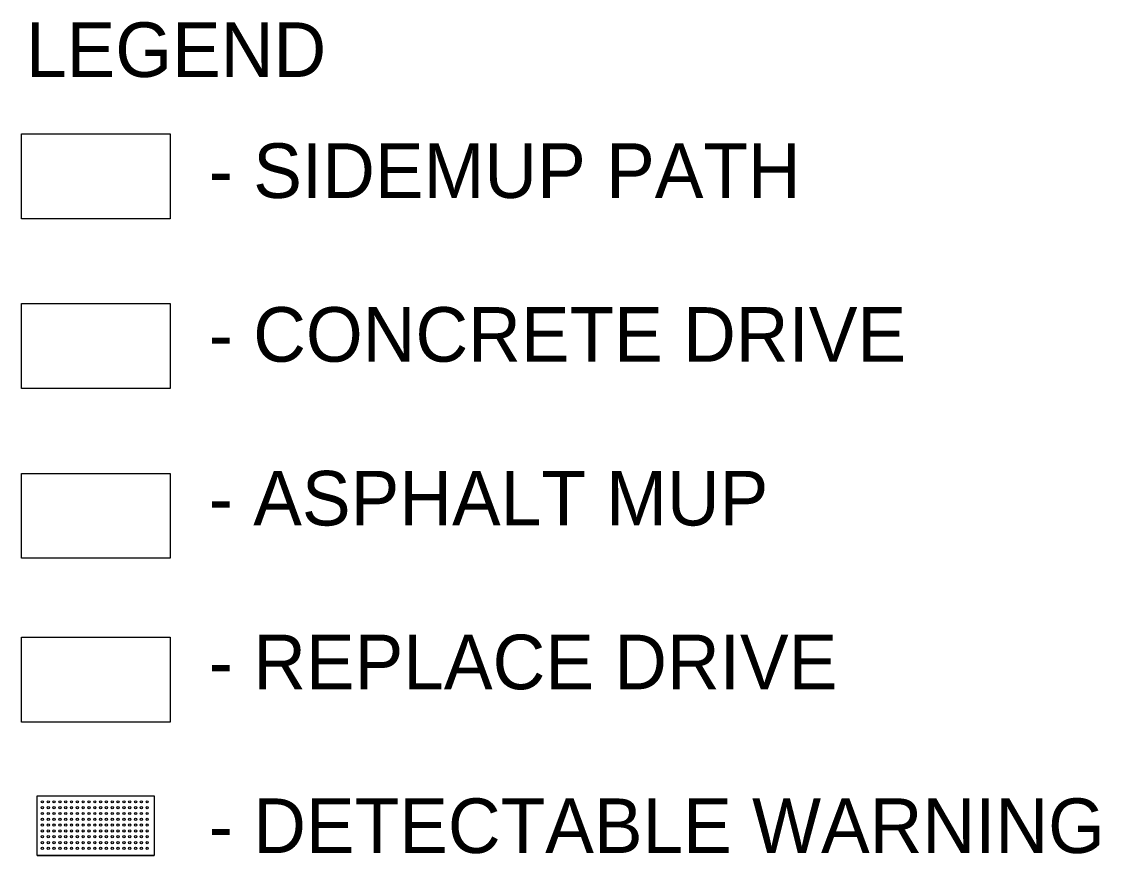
# Model space of a CAD drawing. Extents: x 1387347 to 1392798, y 437934 to 438772.
# Drawn here: x 1389672.4 to 1389727.7, y 438056.4 to 438099.2 of the extents above; entities that cross this region are included whole.
import ezdxf

# ---------------------------------------------------------------- set-up
doc = ezdxf.new("R2010")
doc.units = 0
for name, color, linetype in [('Default', 7, 'Continuous'), ('SC_Scratch6', 7, 'Continuous'), ('SC_Shading1', 7, 'Continuous'), ('SH_Text', 7, 'Continuous')]:
    doc.layers.add(name, color=color, linetype=linetype)

msp = doc.modelspace()

# ---------------------------------------------------------------- linework, layer by layer
at = {"layer": 'Default'}
for p, q in [((1389673.243, 438059.48), (1389679.243, 438059.48)), ((1389673.243, 438056.431), (1389679.243, 438056.431))]:
    msp.add_line(p, q, dxfattribs=at)
for centre in [(1389673.507, 438059.181), (1389673.507, 438058.883), (1389673.805, 438059.181), (1389673.805, 438058.883), (1389674.104, 438059.181), (1389674.104, 438058.883), (1389674.402, 438059.181), (1389674.402, 438058.883), (1389674.701, 438059.181), (1389674.701, 438058.883), (1389674.999, 438059.181), (1389674.999, 438058.883), (1389675.298, 438059.181), (1389675.298, 438058.883), (1389675.596, 438059.181), (1389675.596, 438058.883), (1389675.895, 438059.181), (1389675.895, 438058.883), (1389676.193, 438059.181), (1389676.193, 438058.883), (1389676.492, 438059.181), (1389676.492, 438058.883), (1389676.79, 438059.181), (1389676.79, 438058.883), (1389677.089, 438059.181), (1389677.089, 438058.883), (1389677.387, 438059.181), (1389677.387, 438058.883), (1389677.686, 438059.181), (1389677.686, 438058.883), (1389677.984, 438059.181), (1389677.984, 438058.883), (1389678.283, 438059.181), (1389678.283, 438058.883), (1389678.581, 438059.181), (1389678.581, 438058.883), (1389678.88, 438059.181), (1389678.88, 438058.883), (1389673.507, 438058.584), (1389673.507, 438058.286), (1389673.805, 438058.584), (1389673.805, 438058.286), (1389674.104, 438058.584), (1389674.104, 438058.286), (1389674.402, 438058.584), (1389674.402, 438058.286), (1389674.701, 438058.584), (1389674.701, 438058.286), (1389674.999, 438058.584), (1389674.999, 438058.286), (1389675.298, 438058.584), (1389675.298, 438058.286), (1389675.596, 438058.584), (1389675.596, 438058.286), (1389675.895, 438058.584), (1389675.895, 438058.286), (1389676.193, 438058.584), (1389676.193, 438058.286), (1389676.492, 438058.584), (1389676.492, 438058.286), (1389676.79, 438058.584), (1389676.79, 438058.286), (1389677.089, 438058.584), (1389677.089, 438058.286), (1389677.387, 438058.584), (1389677.387, 438058.286), (1389677.686, 438058.584), (1389677.686, 438058.286), (1389677.984, 438058.584), (1389677.984, 438058.286), (1389678.283, 438058.584), (1389678.283, 438058.286), (1389678.581, 438058.584), (1389678.581, 438058.286), (1389678.88, 438058.584), (1389678.88, 438058.286), (1389673.507, 438057.987), (1389673.507, 438057.689), (1389673.805, 438057.987), (1389673.805, 438057.689), (1389674.104, 438057.987), (1389674.104, 438057.689), (1389674.402, 438057.987), (1389674.402, 438057.689), (1389674.701, 438057.987), (1389674.701, 438057.689), (1389674.999, 438057.987), (1389674.999, 438057.689), (1389675.298, 438057.987), (1389675.298, 438057.689), (1389675.596, 438057.987), (1389675.596, 438057.689), (1389675.895, 438057.987), (1389675.895, 438057.689), (1389676.193, 438057.987), (1389676.193, 438057.689), (1389676.492, 438057.987), (1389676.492, 438057.689), (1389676.79, 438057.987), (1389676.79, 438057.689), (1389677.089, 438057.987), (1389677.089, 438057.689), (1389677.387, 438057.987), (1389677.387, 438057.689), (1389677.686, 438057.987), (1389677.686, 438057.689), (1389677.984, 438057.987), (1389677.984, 438057.689), (1389678.283, 438057.987), (1389678.283, 438057.689), (1389678.581, 438057.987), (1389678.581, 438057.689), (1389678.88, 438057.987), (1389678.88, 438057.689), (1389673.507, 438057.39), (1389673.507, 438057.092), (1389673.805, 438057.39), (1389673.805, 438057.092), (1389674.104, 438057.39), (1389674.104, 438057.092), (1389674.402, 438057.39), (1389674.402, 438057.092), (1389674.701, 438057.39), (1389674.701, 438057.092), (1389674.999, 438057.39), (1389674.999, 438057.092), (1389675.298, 438057.39), (1389675.298, 438057.092), (1389675.596, 438057.39), (1389675.596, 438057.092), (1389675.895, 438057.39), (1389675.895, 438057.092), (1389676.193, 438057.39), (1389676.193, 438057.092), (1389676.492, 438057.39), (1389676.492, 438057.092), (1389676.79, 438057.39), (1389676.79, 438057.092), (1389677.089, 438057.39), (1389677.089, 438057.092), (1389677.387, 438057.39), (1389677.387, 438057.092), (1389677.686, 438057.39), (1389677.686, 438057.092), (1389677.984, 438057.39), (1389677.984, 438057.092), (1389678.283, 438057.39), (1389678.283, 438057.092), (1389678.581, 438057.39), (1389678.581, 438057.092), (1389678.88, 438057.39), (1389678.88, 438057.092), (1389673.507, 438056.793), (1389673.805, 438056.793), (1389674.104, 438056.793), (1389674.402, 438056.793), (1389674.701, 438056.793), (1389674.999, 438056.793), (1389675.298, 438056.793), (1389675.596, 438056.793), (1389675.895, 438056.793), (1389676.193, 438056.793), (1389676.492, 438056.793), (1389676.79, 438056.793), (1389677.089, 438056.793), (1389677.387, 438056.793), (1389677.686, 438056.793), (1389677.984, 438056.793), (1389678.283, 438056.793), (1389678.581, 438056.793), (1389678.88, 438056.793)]:
    msp.add_circle(centre, 0.0572, dxfattribs=at)
at = {"layer": 'SC_Scratch6'}
msp.add_lwpolyline([(1389672.435, 438076.028), (1389680.051, 438076.028), (1389680.051, 438071.674), (1389672.435, 438071.674)], close=True, dxfattribs=at)
at = {"layer": 'SC_Shading1'}
for points in [[(1389672.435, 438093.441), (1389680.051, 438093.441), (1389680.051, 438089.088), (1389672.435, 438089.088)], [(1389672.435, 438084.734), (1389680.051, 438084.734), (1389680.051, 438080.381), (1389672.435, 438080.381)]]:
    msp.add_lwpolyline(points, close=True, dxfattribs=at)
at = {"layer": 'SH_Text'}
for points in [[(1389672.435, 438093.441), (1389680.051, 438093.441), (1389680.051, 438089.088), (1389672.435, 438089.088)], [(1389672.435, 438084.734), (1389680.051, 438084.734), (1389680.051, 438080.381), (1389672.435, 438080.381)], [(1389672.435, 438076.028), (1389680.051, 438076.028), (1389680.051, 438071.674), (1389672.435, 438071.674)], [(1389672.435, 438067.628), (1389680.051, 438067.628), (1389680.051, 438063.274), (1389672.435, 438063.274)], [(1389680.051, 438067.628), (1389680.051, 438063.274), (1389672.435, 438063.274), (1389672.435, 438067.628), (1389672.435, 438067.628), (1389672.435, 438067.628)], [(1389673.243, 438059.48), (1389679.243, 438059.48), (1389679.243, 438056.431), (1389673.243, 438056.431)]]:
    msp.add_lwpolyline(points, close=True, dxfattribs=at)

# ---------------------------------------------------------------- texts
for s, height, p in [('LEGEND', 2.8, (1389672.664, 438096.361)), ('- SIDEMUP PATH', 2.79999, (1389682.032, 438090.155)), ('- CONCRETE DRIVE', 2.79999, (1389682.032, 438081.755)), ('- ASPHALT MUP ', 2.79999, (1389682.032, 438073.355)), ('- REPLACE DRIVE', 2.79999, (1389682.032, 438064.955)), ('- DETECTABLE WARNING', 2.79999, (1389682.032, 438056.555))]:
    msp.add_text(s, height=height, dxfattribs=at).set_placement(p)

doc.saveas('drawing.dxf')
